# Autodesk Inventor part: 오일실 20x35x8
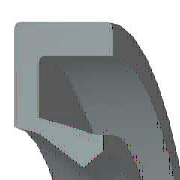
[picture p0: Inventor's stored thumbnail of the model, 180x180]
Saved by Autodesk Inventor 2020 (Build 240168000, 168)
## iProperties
Created: 2012-02
Part Number: 오일실 20x35x8
Material: 고무
Description: 오일 실 - 비스프링, 조립 GA
Document SubType Name: Modeling
Standard: JIS B 2402
Designer: mdu-01
Standards Organization: JIS
Language: ko-KR
Size Designation: 20 35 8 A
Categories: <MemberInstance><Categories><Category DisplayName="샤프트 부품" InternalName="7f7aeb1f-a693-4053-b835-cee3144e0d98" Mnemonic="SHFT"><Category DisplayName="실링" Intern
Density: 0.93 g/cm^3
Appearance: Rubber-Black
IsCustomPart: 1
Author: mdu-01
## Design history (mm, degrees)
body "Solid1"
revolve "회전1" stored, may be unused: angle "d27" = 360 deg
fillet "모깎기1" dims "d28" = 0.4 (= 0.05 x b)
sketch "스케치2"
  geometry: L1 (12.464, -6)-(13.214, -8); L2 (11.464, -5.5)-(12.464, -6); L3 (10, -2.2)-(11.464, -5.5); L4 (11.154, -1.2)-(10, -2.2); L5 (14.5, -7)-(11.154, -1.2); L6 (14.5, -0.4)-(14.5, -7); L7 (16, -0.4)-(14.5, -0.4); L8 (16, 0)-(16, -0.4); L9 (17.5, 0)-(16, 0); L10 (17.5, -8)-(17.5, 0); L11 (13.214, -8)-(17.5, -8); L12 (0, -9.6)-(0, 1.6) reference; L13 (28, 0)-(14, 0) reference
  constraints: 22 end point, 3 horizontal, 3 vertical
  dimensions: "d2" = 8 distance of L10.start L9.start (= b); "d4" = 1.5 distance of L9.start L8.start (= 0.1 x dd - 0.1 x Diam); "d6" = 0.4 distance of L8.start L7.start (= 0.05 x b); "d8" = 1.15385 horizontal distance of L4.start L3.start (= 0.0769231 x dd - 0.0769231 x Diam); "d10" = 1 vertical distance of L5.start L10.start (= 0.125 x b); "d12" = 1.5 distance of L7.start L6.start (= 0.1 x dd - 0.1 x Diam); "d14" = 0.8 vertical distance of L4.start L6.start (= 0.1 x b); "d16" = 4.28571 distance of L1.end L10.start (= 0.285714 x dd - 0.285714 x Diam); "d18" = 0.75 horizontal distance of L1.start L1.end (= 0.05 x dd - 0.05 x Diam); "d20" = 1 vertical distance of L4.start L3.start (= 0.125 x b); "d22" = 2 vertical distance of L1.start L1.end (= 0.25 x b); "d24" = 1 horizontal distance of L2.start L1.start (= 0.0666667 x dd - 0.0666667 x Diam); "d26" = 0.5 vertical distance of L2.start L1.start (= 0.0625 x b); "d29" = 0 distance between parallel lines of L13 L9; "d30" = 10 distance from line of L3.start L12 (= 0.5 x Diam); "d31" = 17.5 distance between parallel lines of L12 L10 (= 0.5 x dd)
other parameters: "dd" = 35 [user parameter; used in 7 equation terms], "b" = 8 [user parameter; used in 8 equation terms], "d1" = 8 (derived), "d3" = 2 (derived), "d5" = 0.4 (derived), "d7" = 1.53846 (derived), "d9" = 1 (derived), "d11" = 2 (derived), "d13" = 0.8 (derived), "d15" = 5.71429 (derived), "d17" = 1 (derived), "d19" = 1 (derived), "d21" = 2 (derived), "d23" = 1.33333 (derived), "d25" = 0.5 (derived), "d32" = 0
